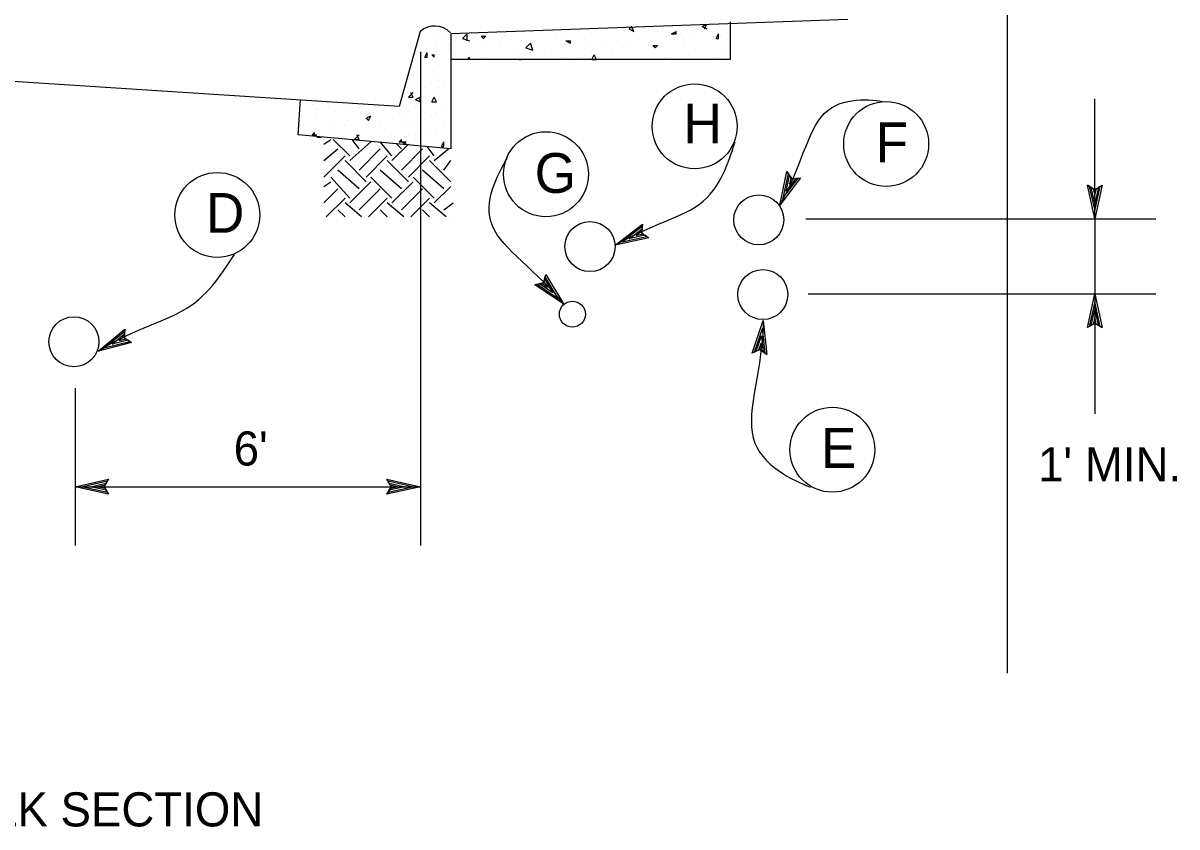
# Model space of a CAD drawing. Extents: x -119017 to -116080, y -104449 to -102845.
# Drawn here: x -118299.2 to -118096.2, y -103268 to -103126.6 of the extents above; entities that cross this region are included whole.
import ezdxf

# ---------------------------------------------------------------- set-up
doc = ezdxf.new("R2010")
doc.units = 0
for name, color, linetype in [('G-MARK', 7, 'Continuous'), ('G-TEXT', 7, 'Continuous'), ('Misc CnstDet(22)', 7, 'Continuous')]:
    doc.layers.add(name, color=color, linetype=linetype)

msp = doc.modelspace()

# ---------------------------------------------------------------- linework, layer by layer
at = {"layer": 'G-MARK'}
for p, q in [((-118229.29, -103131.69), (-118229.29, -103218.5)), ((-118110.65, -103161.04), (-118110.65, -103139.96)), ((-118161.49, -103161.04), (-118099.9, -103161.04)), ((-118110.65, -103161.04), (-118110.65, -103174.27)), ((-118161.08, -103174.27), (-118099.9, -103174.27)), ((-118110.65, -103174.27), (-118110.65, -103195.35)), ((-118290.05, -103190.81), (-118290.05, -103218.5)), ((-118290.05, -103208.17), (-118229.29, -103208.17))]:
    msp.add_line(p, q, dxfattribs=at)
for centre in [(-118181.05, -103144.79), (-118147.36, -103147.89), (-118207.21, -103153.21), (-118265.03, -103160.37), (-118156.82, -103201.66)]:
    msp.add_circle(centre, 7.47, dxfattribs=at)
for points in [[(-118166.09, -103158.67), (-118162.37, -103152.47), (-118160.3, -103138.82), (-118149.97, -103140.06), (-118147.48, -103140.48)], [(-118195.02, -103165.69), (-118188.82, -103161.97), (-118177.25, -103159.91), (-118174.77, -103149.98), (-118173.94, -103147.5)], [(-118204.12, -103176.03), (-118208.67, -103170.24), (-118221.07, -103162.8), (-118215.69, -103153.29), (-118214.04, -103150.4)], [(-118285.97, -103184.3), (-118279.35, -103180.16), (-118268.19, -103178.1), (-118263.23, -103169), (-118261.99, -103167.35)], [(-118168.98, -103178.92), (-118168.98, -103187.19), (-118175.18, -103202.07), (-118163.61, -103207.03), (-118160.71, -103208.27)]]:
    msp.add_open_spline(points, degree=3, dxfattribs=at)
at = {"layer": 'G-TEXT'}
for points in [[(-118162.42, -103153.85), (-118166.09, -103158.67), (-118164.81, -103152.75), (-118164.58, -103153.09), (-118165.52, -103157.42), (-118162.83, -103153.89), (-118163.23, -103153.94), (-118164.95, -103156.2), (-118164.35, -103153.43), (-118164.12, -103153.76), (-118164.38, -103154.96), (-118163.64, -103153.98), (-118163.95, -103154.02), (-118164.81, -103152.75), (-118163.95, -103154.02)], [(-118109.33, -103155.14), (-118110.65, -103161.04), (-118111.95, -103155.14), (-118111.61, -103155.35), (-118110.65, -103159.67), (-118109.68, -103155.35), (-118110.02, -103155.55), (-118110.64, -103158.32), (-118111.26, -103155.56), (-118110.91, -103155.77), (-118110.64, -103156.96), (-118110.37, -103155.76), (-118110.65, -103155.93), (-118111.95, -103155.14), (-118110.65, -103155.93)], [(-118189.11, -103164.4), (-118195.02, -103165.69), (-118190.22, -103162.01), (-118190.27, -103162.42), (-118193.78, -103165.11), (-118189.45, -103164.17), (-118189.79, -103163.94), (-118192.56, -103164.55), (-118190.31, -103162.82), (-118190.35, -103163.23), (-118191.32, -103163.97), (-118190.12, -103163.71), (-118190.38, -103163.53), (-118190.22, -103162.01), (-118190.38, -103163.53)], [(-118207.23, -103170.84), (-118204.12, -103176.03), (-118209.14, -103172.65), (-118208.74, -103172.56), (-118205.06, -103175.04), (-118207.34, -103171.23), (-118207.45, -103171.62), (-118205.99, -103174.06), (-118208.34, -103172.47), (-118207.94, -103172.39), (-118206.93, -103173.07), (-118207.56, -103172.02), (-118207.65, -103172.32), (-118209.14, -103172.65), (-118207.65, -103172.32)], [(-118111.96, -103180.18), (-118110.65, -103174.27), (-118109.34, -103180.18), (-118109.69, -103179.97), (-118110.64, -103175.64), (-118111.61, -103179.97), (-118111.27, -103179.76), (-118110.65, -103176.99), (-118110.03, -103179.76), (-118110.38, -103179.55), (-118110.65, -103178.35), (-118110.92, -103179.55), (-118110.65, -103179.39), (-118109.34, -103180.18), (-118110.65, -103179.39)], [(-118170.94, -103184.65), (-118168.98, -103178.92), (-118168.33, -103184.94), (-118168.66, -103184.69), (-118169.13, -103180.28), (-118170.57, -103184.48), (-118170.2, -103184.31), (-118169.28, -103181.62), (-118168.98, -103184.44), (-118169.3, -103184.19), (-118169.43, -103182.98), (-118169.83, -103184.14), (-118169.55, -103184.01), (-118168.33, -103184.94), (-118169.55, -103184.01)], [(-118280.1, -103182.82), (-118285.97, -103184.3), (-118281.28, -103180.47), (-118281.31, -103180.88), (-118284.75, -103183.68), (-118280.44, -103182.6), (-118280.79, -103182.39), (-118283.54, -103183.08), (-118281.34, -103181.29), (-118281.37, -103181.69), (-118282.32, -103182.47), (-118281.13, -103182.17), (-118281.4, -103182), (-118281.28, -103180.47), (-118281.4, -103182)], [(-118284.15, -103209.49), (-118290.05, -103208.17), (-118284.15, -103206.86), (-118284.36, -103207.21), (-118288.69, -103208.17), (-118284.36, -103209.14), (-118284.57, -103208.79), (-118287.34, -103208.17), (-118284.57, -103207.56), (-118284.78, -103207.91), (-118285.98, -103208.17), (-118284.77, -103208.44), (-118284.94, -103208.17), (-118284.15, -103206.86), (-118284.94, -103208.17)], [(-118235.19, -103206.85), (-118229.29, -103208.17), (-118235.19, -103209.48), (-118234.98, -103209.13), (-118230.66, -103208.17), (-118234.98, -103207.2), (-118234.78, -103207.55), (-118232.01, -103208.17), (-118234.77, -103208.78), (-118234.56, -103208.43), (-118233.37, -103208.17), (-118234.57, -103207.9), (-118234.4, -103208.17), (-118235.19, -103209.48), (-118234.4, -103208.17)]]:
    msp.add_lwpolyline(points, close=True, dxfattribs=at)
at = {"layer": 'Misc CnstDet(22)'}
for p, q in [((-118125.99, -103240.93), (-118125.99, -102921.38)), ((-118154.1, -103126.01), (-118223.96, -103128.49)), ((-118179.73, -103127.25), (-118178.9, -103126.84)), ((-118179.32, -103127.66), (-118178.9, -103126.84)), ((-118174.77, -103126.42), (-118174.77, -103133.04)), ((-118233.06, -103141.3), (-118436.44, -103128.08)), ((-118229.33, -103128.08), (-118233.06, -103141.3)), ((-118229.29, -103127.97), (-118229.29, -103127.97)), ((-118229.29, -103127.97), (-118229.29, -103127.97)), ((-118229.29, -103127.97), (-118229.29, -103127.97)), ((-118226.03, -103128.49), (-118226.03, -103128.49)), ((-118223.96, -103128.49), (-118223.96, -103148.74)), ((-118221.89, -103129.32), (-118221.07, -103128.49)), ((-118221.07, -103129.73), (-118221.07, -103128.49)), ((-118220.24, -103128.49), (-118220.24, -103128.49)), ((-118218.59, -103128.9), (-118218.17, -103129.32)), ((-118218.59, -103128.9), (-118217.76, -103128.9)), ((-118218.17, -103129.32), (-118217.76, -103128.9)), ((-118216.52, -103128.9), (-118216.52, -103128.9)), ((-118209.91, -103128.08), (-118209.91, -103128.08)), ((-118207.01, -103127.66), (-118207.01, -103127.66)), ((-118205.36, -103128.9), (-118205.36, -103128.9)), ((-118204.53, -103128.9), (-118204.53, -103128.9)), ((-118199.16, -103127.66), (-118199.16, -103127.66)), ((-118199.16, -103128.49), (-118199.16, -103128.49)), ((-118198.74, -103127.66), (-118198.74, -103127.66)), ((-118193.78, -103127.66), (-118193.78, -103127.66)), ((-118193.37, -103128.08), (-118193.37, -103128.08)), ((-118192.54, -103127.66), (-118192.13, -103127.25)), ((-118192.54, -103127.66), (-118191.72, -103128.08)), ((-118191.72, -103128.08), (-118192.13, -103127.25)), ((-118187.58, -103128.08), (-118187.58, -103128.08)), ((-118185.93, -103128.9), (-118185.93, -103128.9)), ((-118185.1, -103128.49), (-118184.28, -103128.08)), ((-118185.1, -103128.49), (-118184.28, -103128.49)), ((-118184.28, -103128.49), (-118184.28, -103128.08)), ((-118183.45, -103128.49), (-118183.45, -103128.49)), ((-118181.8, -103128.49), (-118181.8, -103128.49)), ((-118179.73, -103127.25), (-118178.9, -103127.66)), ((-118179.73, -103128.08), (-118179.73, -103128.08)), ((-118177.66, -103128.9), (-118177.66, -103128.9)), ((-118177.25, -103129.32), (-118176.84, -103128.49)), ((-118176.84, -103128.49), (-118176.84, -103128.49)), ((-118176.84, -103129.32), (-118176.84, -103128.49)), ((-118176.42, -103128.9), (-118176.42, -103128.9)), ((-118229.75, -103130.56), (-118229.75, -103130.56)), ((-118226.44, -103129.73), (-118226.44, -103129.73)), ((-118223.13, -103129.73), (-118223.13, -103129.73)), ((-118221.89, -103129.32), (-118220.65, -103129.73)), ((-118220.65, -103129.73), (-118220.65, -103129.73)), ((-118217.76, -103130.97), (-118217.76, -103130.97)), ((-118215.28, -103130.56), (-118215.28, -103130.56)), ((-118211.56, -103129.73), (-118211.56, -103129.73)), ((-118210.73, -103130.97), (-118209.91, -103130.14)), ((-118210.73, -103130.97), (-118209.49, -103131.38)), ((-118209.91, -103129.73), (-118209.91, -103129.73)), ((-118209.49, -103131.38), (-118209.91, -103130.14)), ((-118203.71, -103129.73), (-118202.88, -103130.14)), ((-118203.71, -103129.73), (-118202.88, -103129.73)), ((-118202.88, -103130.14), (-118202.88, -103129.73)), ((-118199.57, -103130.56), (-118199.57, -103130.56)), ((-118196.68, -103130.14), (-118196.68, -103130.14)), ((-118193.78, -103130.97), (-118193.78, -103130.97)), ((-118192.96, -103129.73), (-118192.96, -103129.73)), ((-118189.24, -103130.56), (-118189.24, -103130.56)), ((-118188.41, -103130.56), (-118188.41, -103130.56)), ((-118188.41, -103130.56), (-118188, -103130.97)), ((-118188.41, -103130.56), (-118187.58, -103130.56)), ((-118188, -103130.97), (-118187.58, -103130.56)), ((-118183.04, -103129.32), (-118183.04, -103129.32)), ((-118183.04, -103129.73), (-118183.04, -103129.73)), ((-118177.25, -103129.32), (-118176.84, -103129.32)), ((-118230.16, -103133.04), (-118230.16, -103133.04)), ((-118228.92, -103131.8), (-118228.92, -103131.8)), ((-118228.51, -103132.62), (-118228.09, -103131.8)), ((-118228.51, -103132.62), (-118228.09, -103132.62)), ((-118228.09, -103132.62), (-118228.09, -103131.8)), ((-118227.27, -103132.21), (-118226.85, -103132.62)), ((-118227.27, -103132.21), (-118226.85, -103132.21)), ((-118226.85, -103132.62), (-118226.85, -103132.21)), ((-118226.03, -103132.21), (-118226.03, -103132.21)), ((-118223.96, -103132.21), (-118223.96, -103132.21)), ((-118174.77, -103133.04), (-118223.96, -103133.04)), ((-118223.13, -103132.21), (-118223.13, -103132.21)), ((-118221.07, -103133.04), (-118220.65, -103132.62)), ((-118221.07, -103133.04), (-118221.07, -103133.04)), ((-118220.65, -103131.38), (-118220.65, -103131.38)), ((-118220.65, -103133.04), (-118220.65, -103132.62)), ((-118217.76, -103132.62), (-118217.76, -103132.62)), ((-118212.8, -103132.21), (-118212.8, -103132.21)), ((-118211.97, -103132.62), (-118211.97, -103132.62)), ((-118211.97, -103133.04), (-118211.56, -103133.04)), ((-118211.56, -103133.04), (-118211.56, -103133.04)), ((-118209.91, -103131.8), (-118209.91, -103131.8)), ((-118206.6, -103133.04), (-118206.6, -103133.04)), ((-118206.19, -103131.38), (-118206.19, -103131.38)), ((-118204.53, -103132.62), (-118204.53, -103132.62)), ((-118201.64, -103132.62), (-118201.64, -103132.62)), ((-118199.16, -103131.8), (-118199.16, -103131.8)), ((-118199.16, -103133.04), (-118198.74, -103132.21)), ((-118199.16, -103133.04), (-118198.33, -103133.04)), ((-118198.33, -103133.04), (-118198.74, -103132.21)), ((-118195.44, -103131.38), (-118195.44, -103131.38)), ((-118188.82, -103133.04), (-118188.82, -103133.04)), ((-118186.34, -103132.62), (-118186.34, -103132.62)), ((-118183.04, -103133.04), (-118183.04, -103133.04)), ((-118182.21, -103132.21), (-118182.21, -103132.21)), ((-118177.66, -103132.62), (-118177.66, -103132.62)), ((-118175.59, -103131.38), (-118175.59, -103131.38)), ((-118226.44, -103133.45), (-118226.44, -103133.45)), ((-118226.03, -103133.86), (-118226.03, -103133.86)), ((-118231.4, -103136.34), (-118231.4, -103136.34)), ((-118230.99, -103137.17), (-118230.99, -103137.17)), ((-118226.03, -103135.52), (-118226.03, -103135.52)), ((-118226.03, -103136.76), (-118226.03, -103136.76)), ((-118231.4, -103139.65), (-118230.58, -103138.82)), ((-118230.58, -103139.65), (-118230.99, -103138.82)), ((-118228.51, -103138), (-118228.51, -103138)), ((-118226.03, -103138), (-118226.03, -103138)), ((-118225.2, -103137.58), (-118225.2, -103137.58)), ((-118250.83, -103146.26), (-118250.42, -103140.06)), ((-118250.42, -103140.89), (-118250.42, -103140.89)), ((-118248.35, -103140.89), (-118248.35, -103140.89)), ((-118231.4, -103139.65), (-118231.4, -103139.65)), ((-118231.4, -103139.65), (-118230.58, -103139.65)), ((-118230.16, -103140.06), (-118229.33, -103139.65)), ((-118230.16, -103140.06), (-118229.33, -103140.48)), ((-118229.33, -103140.48), (-118229.33, -103139.65)), ((-118227.27, -103140.48), (-118226.85, -103139.65)), ((-118227.27, -103140.48), (-118226.44, -103140.48)), ((-118226.44, -103140.48), (-118226.85, -103139.65)), ((-118226.03, -103139.24), (-118226.03, -103139.24)), ((-118250, -103142.13), (-118250, -103142.13)), ((-118247.52, -103141.72), (-118247.52, -103141.72)), ((-118244.22, -103142.13), (-118244.22, -103142.13)), ((-118242.56, -103141.3), (-118242.56, -103141.3)), ((-118238.84, -103143.37), (-118238.02, -103142.96)), ((-118238.43, -103142.54), (-118238.43, -103142.54)), ((-118238.43, -103143.78), (-118238.02, -103142.96)), ((-118233.06, -103142.54), (-118233.06, -103142.54)), ((-118231.4, -103142.13), (-118231.4, -103142.13)), ((-118228.92, -103142.13), (-118228.92, -103142.13)), ((-118227.27, -103142.96), (-118227.27, -103142.96)), ((-118226.44, -103142.54), (-118226.44, -103142.54)), ((-118226.44, -103142.96), (-118226.44, -103142.96)), ((-118224.79, -103141.3), (-118224.79, -103141.3)), ((-118247.52, -103143.37), (-118247.52, -103143.37)), ((-118244.63, -103144.2), (-118244.63, -103144.2)), ((-118242.56, -103144.61), (-118242.56, -103144.61)), ((-118242.15, -103143.78), (-118242.15, -103143.78)), ((-118242.15, -103143.78), (-118242.15, -103143.78)), ((-118238.84, -103143.37), (-118238.43, -103143.78)), ((-118238.84, -103145.02), (-118238.84, -103145.02)), ((-118238.02, -103143.37), (-118238.02, -103143.37)), ((-118237.19, -103143.78), (-118237.19, -103143.78)), ((-118236.36, -103143.78), (-118236.36, -103143.78)), ((-118232.64, -103144.2), (-118232.64, -103144.2)), ((-118231.82, -103143.37), (-118231.82, -103143.37)), ((-118230.58, -103144.2), (-118230.58, -103144.2)), ((-118225.2, -103144.2), (-118225.2, -103144.2)), ((-118223.96, -103148.74), (-118250.83, -103146.26)), ((-118248.35, -103146.26), (-118247.94, -103145.85)), ((-118248.35, -103146.26), (-118247.52, -103146.26)), ((-118247.94, -103145.44), (-118247.94, -103145.44)), ((-118247.94, -103146.26), (-118247.94, -103145.85)), ((-118247.52, -103146.68), (-118246.7, -103146.68)), ((-118247.11, -103146.68), (-118247.11, -103146.68)), ((-118246.28, -103147.09), (-118246.28, -103147.09)), ((-118246.28, -103147.92), (-118245.04, -103147.09)), ((-118244.63, -103146.26), (-118244.63, -103146.26)), ((-118241.74, -103149.98), (-118244.63, -103147.09)), ((-118240.08, -103148.74), (-118241.32, -103147.09)), ((-118240.91, -103147.09), (-118240.08, -103146.26)), ((-118240.91, -103147.09), (-118240.08, -103147.09)), ((-118240.08, -103147.09), (-118240.5, -103146.26)), ((-118234.3, -103146.26), (-118234.3, -103146.26)), ((-118233.06, -103147.5), (-118232.64, -103147.09)), ((-118232.64, -103147.5), (-118232.64, -103147.09)), ((-118231.82, -103146.68), (-118231.82, -103146.68)), ((-118231.4, -103146.26), (-118231.4, -103146.26)), ((-118230.16, -103146.26), (-118230.16, -103146.26)), ((-118227.68, -103145.44), (-118227.68, -103145.44)), ((-118226.44, -103145.85), (-118226.44, -103145.85)), ((-118246.28, -103150.81), (-118243.8, -103148.74)), ((-118241.74, -103150.81), (-118238.02, -103147.5)), ((-118240.08, -103152.47), (-118236.36, -103148.74)), ((-118237.19, -103147.5), (-118237.19, -103147.5)), ((-118234.3, -103149.98), (-118236.36, -103147.5)), ((-118235.95, -103147.5), (-118235.95, -103147.5)), ((-118234.3, -103150.81), (-118231.4, -103147.92)), ((-118232.64, -103148.74), (-118233.47, -103147.92)), ((-118233.06, -103147.5), (-118232.64, -103147.5)), ((-118232.64, -103147.5), (-118231.82, -103147.92)), ((-118232.64, -103147.5), (-118231.82, -103147.5)), ((-118232.64, -103152.47), (-118228.92, -103148.74)), ((-118232.23, -103147.92), (-118231.82, -103147.5)), ((-118229.33, -103148.33), (-118229.33, -103148.33)), ((-118226.85, -103149.98), (-118228.09, -103148.33)), ((-118226.85, -103150.81), (-118224.37, -103148.74)), ((-118225.61, -103148.33), (-118225.2, -103147.5)), ((-118225.61, -103148.33), (-118225.2, -103148.33)), ((-118225.2, -103148.33), (-118225.2, -103147.5)), ((-118246.28, -103153.71), (-118242.56, -103149.98)), ((-118238.84, -103154.53), (-118242.56, -103150.81)), ((-118238.84, -103153.71), (-118235.12, -103149.98)), ((-118231.4, -103154.53), (-118235.12, -103150.81)), ((-118231.4, -103153.71), (-118227.68, -103149.98)), ((-118223.96, -103154.53), (-118227.68, -103150.81)), ((-118225.2, -103152.47), (-118223.96, -103150.81)), ((-118240.08, -103155.77), (-118243.8, -103152.47)), ((-118232.64, -103155.77), (-118236.36, -103152.47)), ((-118225.2, -103155.77), (-118228.92, -103152.47)), ((-118246.28, -103154.53), (-118246.28, -103154.53)), ((-118246.28, -103155.36), (-118245.04, -103154.53)), ((-118241.74, -103157.43), (-118245.04, -103153.71)), ((-118241.74, -103158.25), (-118238.02, -103154.53)), ((-118234.3, -103157.43), (-118238.02, -103153.71)), ((-118234.3, -103158.25), (-118230.58, -103154.53)), ((-118226.85, -103157.43), (-118230.58, -103153.71)), ((-118226.85, -103158.25), (-118223.96, -103155.36)), ((-118223.96, -103153.71), (-118223.96, -103153.71)), ((-118246.28, -103158.25), (-118243.8, -103155.77)), ((-118245.87, -103160.73), (-118242.56, -103157.43)), ((-118240.08, -103159.49), (-118236.36, -103155.77)), ((-118238.43, -103160.73), (-118235.12, -103157.43)), ((-118232.64, -103159.49), (-118228.92, -103155.77)), ((-118230.99, -103160.73), (-118227.68, -103157.43)), ((-118242.56, -103160.73), (-118243.8, -103159.49)), ((-118239.67, -103160.73), (-118242.56, -103158.25)), ((-118235.12, -103160.73), (-118236.36, -103159.49)), ((-118232.23, -103160.73), (-118235.12, -103158.25)), ((-118227.68, -103160.73), (-118228.92, -103159.49)), ((-118224.79, -103160.73), (-118227.68, -103158.25)), ((-118225.2, -103159.49), (-118223.55, -103158.25)), ((-118223.55, -103160.73), (-118223.55, -103160.73)), ((-118165.21, -103161.04), (-118165.21, -103161.04)), ((-118164.8, -103174.27), (-118164.8, -103174.27)), ((-118110.65, -103174.27), (-118110.65, -103174.27)), ((-118290.05, -103187.09), (-118290.05, -103187.09)), ((-118229.29, -103208.17), (-118229.29, -103208.17))]:
    msp.add_line(p, q, dxfattribs=at)
for centre, radius in [((-118169.76, -103161.24), 4.4), ((-118199.46, -103165.94), 4.4), ((-118169.06, -103174.38), 4.4), ((-118202.56, -103177.82), 2.29), ((-118290.25, -103182.67), 4.4)]:
    msp.add_circle(centre, radius, dxfattribs=at)
msp.add_arc((-118226.81, -103131.03), 3.88, 44.0345, 130.5276, dxfattribs=at)

# ---------------------------------------------------------------- texts
for s, height, p in [('H', 7, (-118183.02, -103147.8)), ('F', 7, (-118149.19, -103151.11)), ('G', 7, (-118209.19, -103156.49)), ('D', 7, (-118267.03, -103163.51)), ('E', 7, (-118158.84, -103204.85)), ("6'", 6, (-118262.15, -103204.44)), ('TYPICAL ADJACENT SIDEWALK SECTION', 6, (-118416.55, -103267.91))]:
    msp.add_text(s, height=height, dxfattribs=at).set_placement(p)
msp.add_text("1' MIN.", height=6, rotation=0.01, dxfattribs=at).set_placement((-118120.63, -103207.23))

doc.saveas('drawing.dxf')
